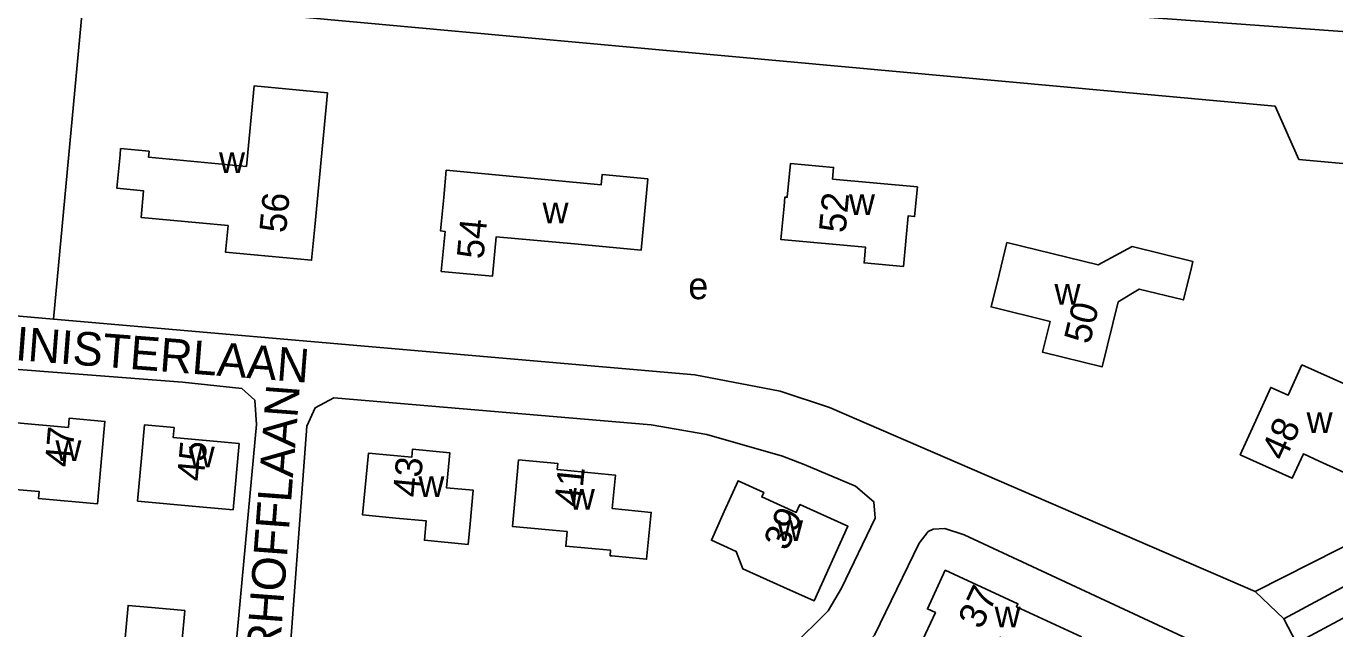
# Model space of a CAD drawing. Extents: x 162427 to 165104, y 384242 to 386287.
# Drawn here: x 163912.8 to 164107.7, y 385145.8 to 385235.6 of the extents above; entities that cross this region are included whole.
import ezdxf

# ---------------------------------------------------------------- set-up
doc = ezdxf.new("R2010")
doc.units = 0
for name, color, linetype in [('BLT_Basislijn', 7, 'Continuous'), ('BLT_Bebouwing', 7, 'Continuous'), ('BLT_Centroide', 7, 'Continuous'), ('BLT_Huisnummer', 7, 'Continuous'), ('BLT_Straatnaam', 7, 'Continuous')]:
    doc.layers.add(name, color=color, linetype=linetype)

msp = doc.modelspace()

# ---------------------------------------------------------------- linework, layer by layer
at = {"layer": 'BLT_Basislijn'}
for p, q in [((163907.27, 385192.8), (163916.82, 385191.96)), ((164100.08, 385147.29), (164157.64, 385178.38)), ((164095.83, 385151.36), (164100.08, 385147.29)), ((164100.08, 385147.29), (164101.95, 385143.68))]:
    msp.add_line(p, q, dxfattribs=at)
for points in [[(163719.72, 385227.97), (163758.68, 385247.63), (163770.66, 385252.86), (163778.27, 385255.65), (163784.87, 385257.24), (163794.66, 385258.7), (163805.08, 385259.08), (163818.56, 385258.83), (163833.99, 385257.58), (163913.29, 385250.18), (164037.15, 385240.92), (164075.9, 385237.19), (164131.43, 385233.17)], [(163916.82, 385191.96), (163921.31, 385239.96), (164098.8, 385223.67), (164102.32, 385215.75), (164119.72, 385214.13), (164129.68, 385209.43), (164130.16, 385208.88), (164141.58, 385174.96), (164141.42, 385174.48), (164095.83, 385151.36)], [(164095.83, 385151.36), (164032.42, 385178.79), (164025.07, 385181.24), (164012.37, 385183.66), (163916.82, 385191.96)], [(163888.92, 385099.03), (163892.17, 385100.78), (163883.54, 385118.73), (163882.35, 385122.09), (163882.92, 385132.31), (163886.87, 385181.05), (163887.24, 385182.8), (163888.99, 385185.31), (163890.71, 385185.84), (163892.89, 385185.88), (163936.03, 385182.55), (163944.89, 385181.59), (163946.8, 385179.9), (163947.05, 385176.26), (163943.23, 385134.98), (163943.39, 385129.54), (163944.73, 385123.43), (163945.53, 385121.28), (163955.66, 385101.15)], [(164028.62, 385170.3), (164036.3, 385167.05), (164039, 385164.73), (164039.21, 385162.28), (164034.17, 385151.84), (164032.22, 385148.46), (164026.69, 385143.03), (163964.96, 385112.45), (163961.43, 385111.99), (163958.89, 385113.06), (163956.66, 385116.27), (163952.37, 385125.43), (163951.27, 385132.11), (163954.57, 385176.02), (163955.8, 385178.75), (163958.6, 385180.24), (164005.85, 385176.18), (164014.12, 385174.75), (164025.4, 385171.51), (164028.62, 385170.3)], [(164101.95, 385143.68), (164139.93, 385164.03), (164144.2, 385165.75), (164147.78, 385165.76), (164157.35, 385163.13)], [(163961.08, 385103.59), (164032.42, 385138.66), (164035.6, 385140.95), (164039.13, 385144.88), (164045.75, 385158.55), (164047.12, 385160.3), (164047.83, 385160.67), (164049.6, 385160.76), (164052.46, 385159.79), (164087.89, 385143.32)]]:
    msp.add_lwpolyline(points, dxfattribs=at)
at = {"layer": 'BLT_Bebouwing'}
for points in [[(163955.73, 385205.7), (163957.62, 385225.67), (163946.7, 385226.7), (163945.56, 385214.71), (163930.96, 385216.09), (163931.05, 385216.96), (163926.82, 385217.36), (163926.73, 385216.42), (163926.26, 385211.45), (163930.24, 385211.07), (163929.86, 385207.11), (163942.83, 385205.88), (163942.46, 385201.93), (163955.26, 385200.72), (163955.73, 385205.7)], [(164045.49, 385211.68), (164032.86, 385212.83), (164033.02, 385214.55), (164026.58, 385215.14), (164026.12, 385210.11), (164025.76, 385210.15), (164025.64, 385208.79), (164025.18, 385203.81), (164037.79, 385202.66), (164037.57, 385200.32), (164043.42, 385199.78), (164044.11, 385207.33), (164045.09, 385207.24), (164045.49, 385211.68)], [(164005.36, 385212.88), (163998.55, 385213.52), (163998.41, 385211.98), (163975.32, 385214.13), (163974.94, 385210.06), (163974.48, 385205.09), (163975.15, 385205.02), (163974.59, 385199.05), (163982.21, 385198.35), (163982.76, 385204.23), (163994.42, 385203.15), (164004.37, 385202.23), (164005.36, 385212.88)], [(164086.31, 385199.67), (164086.52, 385200.54), (164077.49, 385202.76), (164072.42, 385200.03), (164058.84, 385203.37), (164057.68, 385198.62), (164056.48, 385193.77), (164065.27, 385191.61), (164064.14, 385187.01), (164073.01, 385184.84), (164075.39, 385194.51), (164078.55, 385196.43), (164085.11, 385194.81), (164086.31, 385199.67)], [(164102.76, 385185.15), (164109.75, 385181.99), (164109.49, 385181.41), (164126.78, 385173.58), (164124.56, 385168.68), (164113.65, 385173.62), (164111.17, 385168.17), (164105.36, 385170.8), (164102.99, 385171.88), (164101.34, 385168.24), (164093.59, 385171.75), (164095.65, 385176.31), (164098.12, 385181.77), (164100.7, 385180.6), (164102.76, 385185.15)], [(163924.03, 385171.74), (163923.39, 385164.43), (163914.6, 385165.21), (163914.7, 385166.26), (163909.93, 385166.68), (163910.36, 385171.55), (163910.8, 385176.53), (163919.05, 385175.81), (163919.17, 385177.18), (163924.47, 385176.72), (163924.03, 385171.74)], [(163938.58, 385164), (163943.56, 385163.55), (163944.46, 385173.41), (163934.66, 385174.3), (163934.79, 385175.8), (163930.39, 385176.2), (163929.94, 385171.22), (163929.36, 385164.84), (163938.58, 385164)], [(163978.87, 385161.46), (163978.58, 385158.38), (163972.08, 385158.99), (163972.35, 385161.89), (163967.83, 385162.31), (163962.86, 385162.77), (163963.72, 385171.97), (163970.18, 385171.36), (163970.29, 385172.56), (163975.84, 385172.04), (163975.35, 385166.82), (163979.34, 385166.44), (163978.87, 385161.46)], [(164000, 385168.74), (164000.55, 385168.69), (164000.05, 385163.74), (164005.85, 385163.16), (164005.35, 385158.19), (164005.15, 385156.18), (164000, 385156.66), (163999.73, 385156.68), (163999.8, 385157.51), (163993.13, 385158.11), (163993.33, 385160.3), (163985.21, 385161.03), (163985.65, 385165.99), (163986.1, 385170.97), (163991.92, 385170.45), (163991.84, 385169.56), (164000, 385168.74)], [(164025.57, 385152), (164030.12, 385149.95), (164035.14, 385161.09), (164027.99, 385164.31), (164027.46, 385163.14), (164022.31, 385165.46), (164022.61, 385166.14), (164018.79, 385167.86), (164016.74, 385163.3), (164014.81, 385159.01), (164018.52, 385157.34), (164019.48, 385154.74), (164025.57, 385152)], [(164067.83, 385140.05), (164069.93, 385144.59), (164060.26, 385149.08), (164060.46, 385149.51), (164049.66, 385154.53), (164046.99, 385148.77), (164048.19, 385148.21), (164045.24, 385141.86), (164049.78, 385139.76), (164054.54, 385137.55), (164057.79, 385144.55), (164067.76, 385139.92), (164067.83, 385140.05)], [(163940.18, 385135.69), (163940.87, 385143.21), (163935.93, 385143.66), (163936.38, 385148.52), (163931.4, 385148.98), (163927.93, 385149.3), (163926.79, 385136.92)]]:
    msp.add_lwpolyline(points, dxfattribs=at)

# ---------------------------------------------------------------- texts
at = {"layer": 'BLT_Centroide'}
for s, p in [('w', (163941.48, 385213.72)), ('w', (163989.67, 385206.25)), ('w', (164035.31, 385207.47)), ('e', (164011.38, 385194.92)), ('w', (164065.92, 385194.09)), ('w', (164103.47, 385174.97)), ('w', (163917.12, 385170.81)), ('w', (163936.98, 385169.88)), ('w', (163971.18, 385165.47)), ('w', (163993.59, 385163.56)), ('w', (164024.61, 385158.91)), ('w', (164057, 385146.03))]:
    msp.add_text(s, height=4, dxfattribs=at).set_placement(p)
at = {"layer": 'BLT_Huisnummer'}
for s, rotation, p in [('56', 84.5992, (163951.45, 385204.7)), ('52', 84.7912, (164034.8, 385204.71)), ('54', 84.6987, (163980.86, 385200.8)), ('50', 76.2037, (164071.16, 385188.09)), ('47', 84.9825, (163919.49, 385169.79)), ('48', 65.6335, (164100.2, 385170.64)), ('45', 84.804, (163939.18, 385167.69)), ('43', 84.6406, (163971.32, 385165.3)), ('41', 84.2217, (163995.37, 385163.86)), ('39', 65.7582, (164026.08, 385157.28)), ('37', 65.083, (164055.02, 385145.58))]:
    msp.add_text(s, height=4, rotation=rotation, dxfattribs=at).set_placement(p)
at = {"layer": 'BLT_Straatnaam'}
for s, rotation, p in [('MINISTERLAAN', 355.5702, (163905.48, 385186.29)), ('SUURHOFFLAAN', 85.6985, (163949.42, 385127.52))]:
    msp.add_text(s, height=5, rotation=rotation, dxfattribs=at).set_placement(p)

doc.saveas('drawing.dxf')
